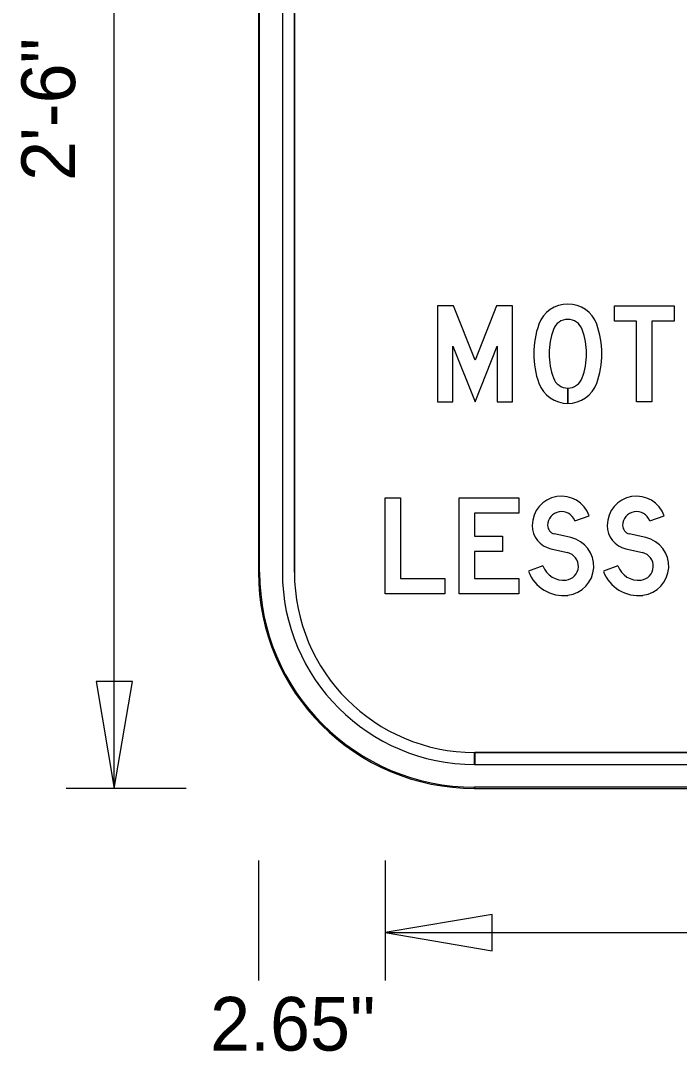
# Model space of a CAD drawing. Extents: x 0 to 770, y 0 to 495.
# Drawn here: x 610.2 to 653.1, y 197.5 to 264.7 of the extents above; entities that cross this region are included whole.
import ezdxf

# ---------------------------------------------------------------- set-up
doc = ezdxf.new("R2010")
doc.units = 0
for name, color, linetype in [('Default', 7, 'Continuous'), ('Dimension', 7, 'Continuous'), ('GSBWFill', 7, 'Continuous'), ('GSColorFill', 7, 'Continuous'), ('GSDims', 7, 'Continuous'), ('GSOutline', 7, 'Continuous')]:
    doc.layers.add(name, color=color, linetype=linetype)

msp = doc.modelspace()

# ---------------------------------------------------------------- linework, layer by layer
at = {"layer": 'Default'}
for p, q in [((645.875, 240.766), (645.875, 239.764)), ((645.875, 240.766), (645.875, 239.764)), ((645.876, 239.764), (645.876, 240.766)), ((645.876, 239.764), (645.876, 240.766)), ((646.326, 232.111), (647.273, 232.439)), ((646.326, 232.111), (647.273, 232.439)), ((646.326, 232.111), (647.273, 232.439)), ((651.21, 232.111), (652.156, 232.439)), ((651.21, 232.111), (652.156, 232.439)), ((651.21, 232.111), (652.156, 232.439)), ((646.08, 231.018), (644.999, 231.264)), ((646.08, 231.018), (644.999, 231.264)), ((646.08, 231.018), (644.999, 231.264)), ((650.963, 231.018), (649.883, 231.264)), ((650.963, 231.018), (649.883, 231.264)), ((650.963, 231.018), (649.883, 231.264)), ((644.777, 230.287), (645.858, 230.041)), ((644.777, 230.287), (645.858, 230.041)), ((644.777, 230.287), (645.858, 230.041)), ((649.661, 230.287), (650.741, 230.041)), ((649.661, 230.287), (650.741, 230.041)), ((649.661, 230.287), (650.741, 230.041)), ((644.246, 229.177), (643.309, 228.824)), ((644.246, 229.177), (643.309, 228.824)), ((644.246, 229.177), (643.309, 228.824)), ((649.129, 229.177), (648.192, 228.824)), ((649.129, 229.177), (648.192, 228.824)), ((649.129, 229.177), (648.192, 228.824))]:
    msp.add_line(p, q, dxfattribs=at)
for points in [[(642.275, 239.874), (642.275, 246.135), (641.239, 246.135), (639.834, 242.591), (638.429, 246.135), (637.392, 246.135), (637.392, 239.874), (638.394, 239.874), (638.394, 243.505), (639.834, 239.874), (641.274, 243.505), (641.274, 239.874)], [(642.275, 239.874), (642.275, 246.135), (641.239, 246.135), (639.834, 242.591), (638.429, 246.135), (637.392, 246.135), (637.392, 239.874), (638.394, 239.874), (638.394, 243.505), (639.834, 239.874), (641.274, 243.505), (641.274, 239.874)], [(642.275, 239.874), (642.275, 246.135), (641.239, 246.135), (639.834, 242.591), (638.429, 246.135), (637.392, 246.135), (637.392, 239.874), (638.394, 239.874), (638.394, 243.505), (639.834, 239.874), (641.274, 243.505), (641.274, 239.874)], [(652.794, 246.135), (652.794, 245.133), (651.354, 245.133), (651.354, 239.874), (650.352, 239.874), (650.352, 245.133), (648.912, 245.133), (648.912, 246.135)], [(652.794, 246.135), (652.794, 245.133), (651.354, 245.133), (651.354, 239.874), (650.352, 239.874), (650.352, 245.133), (648.912, 245.133), (648.912, 246.135)], [(652.794, 246.135), (652.794, 245.133), (651.354, 245.133), (651.354, 239.874), (650.352, 239.874), (650.352, 245.133), (648.912, 245.133), (648.912, 246.135)], [(634.982, 228.354), (637.862, 228.354), (637.862, 227.352), (633.98, 227.352), (633.98, 233.613), (634.982, 233.613)], [(634.982, 228.354), (637.862, 228.354), (637.862, 227.352), (633.98, 227.352), (633.98, 233.613), (634.982, 233.613)], [(634.982, 228.354), (637.862, 228.354), (637.862, 227.352), (633.98, 227.352), (633.98, 233.613), (634.982, 233.613)], [(642.682, 232.611), (639.802, 232.611), (639.802, 231.109), (641.623, 231.109), (641.623, 230.107), (639.802, 230.107), (639.802, 228.354), (642.682, 228.354), (642.682, 227.352), (638.801, 227.352), (638.801, 233.613), (642.682, 233.613)], [(642.682, 232.611), (639.802, 232.611), (639.802, 231.109), (641.623, 231.109), (641.623, 230.107), (639.802, 230.107), (639.802, 228.354), (642.682, 228.354), (642.682, 227.352), (638.801, 227.352), (638.801, 233.613), (642.682, 233.613)], [(642.682, 232.611), (639.802, 232.611), (639.802, 231.109), (641.623, 231.109), (641.623, 230.107), (639.802, 230.107), (639.802, 228.354), (642.682, 228.354), (642.682, 227.352), (638.801, 227.352), (638.801, 233.613), (642.682, 233.613)]]:
    msp.add_lwpolyline(points, close=True, dxfattribs=at)
for centre, radius, start, end in [((645.469, 231.813), 1.91, 19.13948, 180), ((645.469, 231.813), 1.91, 19.13948, 180), ((645.469, 231.813), 1.91, 19.13948, 180), ((650.352, 231.813), 1.91, 19.13948, 180), ((650.352, 231.813), 1.91, 19.13948, 180), ((650.352, 231.813), 1.91, 19.13948, 180), ((645.469, 231.813), 0.908, 19.13948, 180), ((645.469, 231.813), 0.908, 19.13948, 180), ((645.469, 231.813), 0.908, 19.13948, 180), ((650.352, 231.813), 0.908, 19.13948, 180), ((650.352, 231.813), 0.908, 19.13948, 180), ((650.352, 231.813), 0.908, 19.13948, 180), ((645.124, 231.813), 1.565, 180, 257.19149), ((645.124, 231.813), 1.565, 180, 257.19149), ((645.124, 231.813), 1.565, 180, 257.19149), ((645.124, 231.813), 0.563, 180, 257.19149), ((645.124, 231.813), 0.563, 180, 257.19149), ((645.124, 231.813), 0.563, 180, 257.19149), ((650.008, 231.813), 1.565, 180, 257.19149), ((650.008, 231.813), 1.565, 180, 257.19149), ((650.008, 231.813), 1.565, 180, 257.19149), ((650.008, 231.813), 0.563, 180, 257.19149), ((650.008, 231.813), 0.563, 180, 257.19149), ((650.008, 231.813), 0.563, 180, 257.19149), ((645.656, 229.156), 1.91, 276.78539, 77.19149), ((645.656, 229.156), 1.91, 276.78539, 77.19149), ((645.656, 229.156), 1.91, 276.78539, 77.19149), ((650.54, 229.156), 1.91, 276.78539, 77.19149), ((650.54, 229.156), 1.91, 276.78539, 77.19149), ((650.54, 229.156), 1.91, 276.78539, 77.19149), ((645.656, 229.156), 0.908, 276.78539, 77.19149), ((645.656, 229.156), 0.908, 276.78539, 77.19149), ((645.656, 229.156), 0.908, 276.78539, 77.19149), ((650.54, 229.156), 0.908, 276.78539, 77.19149), ((650.54, 229.156), 0.908, 276.78539, 77.19149), ((650.54, 229.156), 0.908, 276.78539, 77.19149), ((645.593, 229.684), 1.44, 200.64423, 276.78539), ((645.593, 229.684), 1.44, 200.64423, 276.78539), ((645.593, 229.684), 1.44, 200.64423, 276.78539), ((650.477, 229.684), 1.44, 200.64423, 276.78539), ((650.477, 229.684), 1.44, 200.64423, 276.78539), ((650.477, 229.684), 1.44, 200.64423, 276.78539), ((645.593, 229.684), 2.442, 200.64423, 276.78539), ((645.593, 229.684), 2.442, 200.64423, 276.78539), ((645.593, 229.684), 2.442, 200.64423, 276.78539), ((650.477, 229.684), 2.442, 200.64423, 276.78539), ((650.477, 229.684), 2.442, 200.64423, 276.78539), ((650.477, 229.684), 2.442, 200.64423, 276.78539)]:
    msp.add_arc(centre, radius, start, end, dxfattribs=at)
for centre, major_axis, start_param, end_param in [((645.875, 244.241), (0, 2.003), 5.063177, 7.503193), ((645.875, 244.241), (0, 2.003), 5.063177, 7.503193), ((645.875, 244.241), (0, 2.003), 5.063177, 7.503193), ((645.875, 244.241), (0, 1.002), 5.063177, 7.503193), ((645.875, 244.241), (0, 1.002), 5.063177, 7.503193), ((645.875, 244.241), (0, 1.002), 5.063177, 7.503193), ((649.255, 243.004), (0, 5.602), 1.220008, 1.921585), ((649.255, 243.004), (0, 5.602), 1.220008, 1.921585), ((649.255, 243.004), (0, 5.602), 1.220008, 1.921585), ((649.255, 243.004), (0, 4.6), 1.220008, 1.921585), ((649.255, 243.004), (0, 4.6), 1.220008, 1.921585), ((649.255, 243.004), (0, 4.6), 1.220008, 1.921585), ((642.496, 243.004), (0, 4.6), 4.361601, 5.063177), ((642.496, 243.004), (0, 4.6), 4.361601, 5.063177), ((642.496, 243.004), (0, 4.6), 4.361601, 5.063177), ((642.496, 243.004), (0, 5.602), 4.361601, 5.063177), ((642.496, 243.004), (0, 5.602), 4.361601, 5.063177), ((642.496, 243.004), (0, 5.602), 4.361601, 5.063177), ((645.875, 241.768), (0, 1.002), 1.921585, 4.361601), ((645.875, 241.768), (0, 1.002), 1.921585, 3.141593), ((645.875, 241.768), (0, 1.002), 1.921585, 3.141593), ((645.875, 241.768), (0, 1.002), 3.141905, 4.361601), ((645.875, 241.768), (0, 1.002), 3.141905, 4.361601), ((645.875, 241.768), (0, 2.003), 1.921585, 4.361601), ((645.875, 241.768), (0, 2.003), 1.921585, 3.141593), ((645.875, 241.768), (0, 2.003), 1.921585, 3.141593), ((645.875, 241.768), (0, 2.003), 3.141749, 4.361601), ((645.875, 241.768), (0, 2.003), 3.141749, 4.361601)]:
    msp.add_ellipse(centre, major_axis=major_axis, ratio=0.999993, start_param=start_param, end_param=end_param, dxfattribs=at)
at = {"layer": 'Dimension'}
for points in [[(616.324, 214.674), (617.506, 221.648), (615.143, 221.648)], [(633.98, 205.283), (640.954, 204.101), (640.954, 206.464)]]:
    msp.add_lwpolyline(points, close=True, dxfattribs=at)
at = {"layer": 'GSBWFill'}
for p, q in [((625.715, 294.5), (625.715, 228.761)), ((627.281, 294.5), (627.281, 228.761)), ((628.063, 228.761), (628.063, 294.5)), ((639.802, 216.239), (639.802, 217.022)), ((705.541, 217.022), (639.81, 217.022)), ((639.81, 217.022), (639.81, 216.239)), ((639.81, 216.239), (705.541, 216.239)), ((639.802, 214.674), (705.541, 214.674))]:
    msp.add_line(p, q, dxfattribs=at)
for radius in [14.087, 12.522, 11.739]:
    msp.add_arc((639.802, 228.761), radius, 180, 270, dxfattribs=at)
at = {"layer": 'GSColorFill'}
for p, q in [((625.715, 294.5), (625.715, 228.761)), ((625.715, 294.5), (625.715, 228.761)), ((625.794, 228.761), (625.794, 294.5)), ((627.281, 294.5), (627.281, 228.761)), ((628.063, 228.761), (628.063, 294.5)), ((639.802, 216.239), (639.802, 217.022)), ((705.541, 217.022), (639.81, 217.022)), ((639.81, 217.022), (639.81, 216.239)), ((639.81, 216.239), (705.541, 216.239)), ((639.802, 214.674), (639.802, 214.752)), ((639.802, 214.674), (705.541, 214.674)), ((705.541, 214.752), (639.803, 214.752)), ((639.803, 214.752), (639.803, 214.674)), ((639.803, 214.674), (705.541, 214.674))]:
    msp.add_line(p, q, dxfattribs=at)
for radius in [14.087, 14.087, 14.009, 12.522, 11.739]:
    msp.add_arc((639.802, 228.761), radius, 180, 270, dxfattribs=at)
at = {"layer": 'GSDims'}
for p, q in [((616.324, 214.674), (616.324, 308.587)), ((621.02, 214.674), (613.194, 214.674)), ((625.715, 209.978), (625.715, 202.152)), ((633.98, 209.978), (633.98, 202.152)), ((633.98, 209.978), (633.98, 202.152)), ((625.715, 206.065), (625.715, 202.152)), ((633.98, 205.283), (711.364, 205.283))]:
    msp.add_line(p, q, dxfattribs=at)
at = {"layer": 'GSOutline'}
for p, q in [((625.715, 294.5), (625.715, 228.761)), ((627.281, 294.5), (627.281, 228.761)), ((628.063, 294.5), (628.063, 228.761)), ((639.802, 217.022), (705.541, 217.022)), ((639.802, 216.239), (705.541, 216.239)), ((639.802, 214.674), (705.541, 214.674))]:
    msp.add_line(p, q, dxfattribs=at)
for radius in [14.087, 12.522, 11.739]:
    msp.add_arc((639.802, 228.761), radius, 180, 270, dxfattribs=at)

# ---------------------------------------------------------------- texts
at = {"layer": 'Default'}
msp.add_text('2\'-6"', height=3.5, rotation=90, dxfattribs=at).set_placement((613.776, 254.269))
msp.add_text('2.65"', height=3.5, dxfattribs=at).set_placement((622.571, 197.587))

doc.saveas('drawing.dxf')
